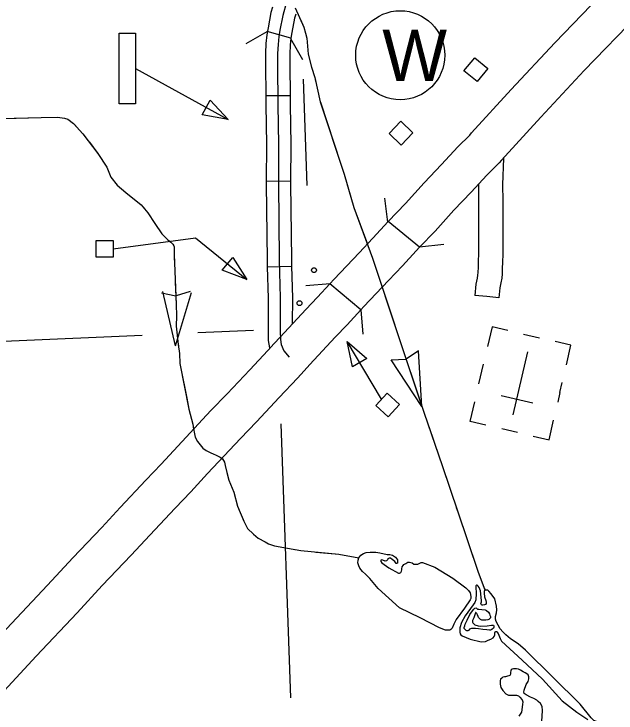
# Model space of a CAD drawing. Extents: x 1084508 to 1142749, y 1057638 to 1093403.
# Drawn here: x 1114355 to 1115521, y 1060091 to 1061446 of the extents above; entities that cross this region are included whole.
import ezdxf

# ---------------------------------------------------------------- set-up
doc = ezdxf.new("R2010")
doc.units = 0
for name, color, linetype in [('Level 15', 7, 'Continuous'), ('Level 32', 7, 'Continuous'), ('Level 35', 7, 'Continuous'), ('Level 37', 7, 'Continuous'), ('Level 38', 7, 'Continuous'), ('Level 43', 7, 'Continuous'), ('Level 46', 7, 'Continuous'), ('Level 5', 7, 'Continuous'), ('Level 56', 7, 'Continuous'), ('Level 57', 7, 'Continuous')]:
    doc.layers.add(name, color=color, linetype=linetype)

msp = doc.modelspace()

# ---------------------------------------------------------------- linework, layer by layer
at = {"layer": 'Level 15'}
for p, q in [((1115140.9, 1060993.5), (1115079.6, 1061043.1)), ((1115027.2, 1060872.2), (1114967, 1060922.7))]:
    msp.add_line(p, q, dxfattribs=at)
for points in [[(1115241.6, 1061215.1), (1115318.3, 1061299.1), (1115402.8, 1061389.8), (1115508.4, 1061499.3)], [(1115564.9, 1061444.8), (1115459.8, 1061335.8), (1115376, 1061245.9), (1115299.6, 1061162.2)], [(1115079.6, 1061043.1), (1115113.2, 1061078.1), (1115149.4, 1061118.6), (1115183.4, 1061154.1), (1115214.7, 1061187.9), (1115237.9, 1061211), (1115241.6, 1061215.1)], [(1115299.6, 1061162.2), (1115294.7, 1061156.8), (1115271.3, 1061133.5), (1115240.6, 1061100.3), (1115207, 1061065.3), (1115170.8, 1061024.8), (1115140.9, 1060993.5)], [(1115079.6, 1061043.1), (1115050.1, 1061010.9), (1115023.6, 1060982.9), (1114975.4, 1060931.8), (1114967, 1060922.7)], [(1115140.9, 1060993.5), (1115134, 1060986.4), (1115107.6, 1060957.4), (1115080.5, 1060928.9), (1115032.8, 1060878.3), (1115027.2, 1060872.2)], [(1114967, 1060922.7), (1114943.2, 1060896.7), (1114920.3, 1060872.8), (1114870.3, 1060819.1), (1114859, 1060806.8)], [(1114916.9, 1060753.8), (1114928, 1060765.9), (1114977.3, 1060818.9), (1115000.4, 1060843), (1115027.2, 1060872.2)], [(1114859, 1060806.8), (1114846.4, 1060793), (1114811.6, 1060755.8), (1114767.8, 1060709.4), (1114736.5, 1060676.9), (1114672.2, 1060608), (1114640.1, 1060572.8), (1114610, 1060541.7), (1114560.6, 1060488.9), (1114524.7, 1060450.4), (1114468.5, 1060391.1), (1114419.6, 1060338.5), (1114340.5, 1060254), (1114270.6, 1060179), (1114255.7, 1060163.4)], [(1114312.6, 1060109.4), (1114327.7, 1060125.1), (1114397.9, 1060200.5), (1114477, 1060285), (1114525.8, 1060337.5), (1114581.8, 1060396.7), (1114617.9, 1060435.3), (1114666.9, 1060487.6), (1114697.3, 1060519.1), (1114729.8, 1060554.8), (1114793.4, 1060622.8), (1114824.6, 1060655.2), (1114868.9, 1060702.1), (1114904, 1060739.7), (1114916.9, 1060753.8)]]:
    msp.add_lwpolyline(points, dxfattribs=at)
at = {"layer": 'Level 32'}
for p, q in [((1114891.2, 1061399), (1114845.6, 1061411.4)), ((1114842.6, 1061287.4), (1114889.7, 1061287.9)), ((1114843.6, 1061122.1), (1114890.7, 1061121.8)), ((1114845.6, 1060955.6), (1114892.7, 1060956.8))]:
    msp.add_line(p, q, dxfattribs=at)
for points in [[(1114883, 1061468.7), (1114875.6, 1061443), (1114870.2, 1061414.2), (1114867.8, 1061402.1), (1114866.4, 1061386.8), (1114865.5, 1061369), (1114865.4, 1061346.1), (1114866.3, 1061270.2), (1114867.6, 1061192.2), (1114867.1, 1061116.8), (1114868.8, 1060968.9), (1114870.8, 1060895.2), (1114870.5, 1060830.8), (1114871, 1060814.7), (1114872.7, 1060804.9), (1114877.9, 1060792.8), (1114887.9, 1060780.3)], [(1114855.6, 1061458.7), (1114852.7, 1061448.5), (1114847.1, 1061418.6), (1114844.5, 1061405.5), (1114842.9, 1061388.5), (1114842, 1061369.6), (1114841.9, 1061346), (1114842.6, 1061287.4)], [(1114900.8, 1061445.6), (1114898.5, 1061437.6), (1114893.3, 1061409.8), (1114891.2, 1061398.8), (1114889.9, 1061385.1), (1114889.1, 1061368.4), (1114889, 1061346.2), (1114889.7, 1061287.9)], [(1114842.6, 1061287.4), (1114842.8, 1061269.9), (1114844, 1061192.1), (1114843.6, 1061122.1)], [(1114889.7, 1061287.9), (1114889.9, 1061270.5), (1114891.1, 1061192.3), (1114890.7, 1061121.8)], [(1114843.6, 1061122.1), (1114843.6, 1061116.7), (1114845.3, 1060968.4), (1114845.6, 1060955.6)], [(1114890.7, 1061121.8), (1114890.7, 1061116.9), (1114892.4, 1060969.3), (1114892.7, 1060956.8)], [(1114845.6, 1060955.6), (1114847.2, 1060895), (1114847, 1060830.5), (1114847.5, 1060812.4), (1114849.9, 1060798.2), (1114850.3, 1060797.3)], [(1114892.7, 1060956.8), (1114894.3, 1060895.5), (1114894.1, 1060844.7)]]:
    msp.add_lwpolyline(points, dxfattribs=at)
at = {"layer": 'Level 35'}
for points in [[(1115239, 1060309.7), (1115227.6, 1060294), (1115211.9, 1060271.6), (1115207.1, 1060262.5), (1115204.2, 1060255.2), (1115201.6, 1060252.6), (1115199.1, 1060251.5), (1115194, 1060251.1), (1115190.7, 1060251.1), (1115179.3, 1060255.9), (1115141.6, 1060274.9), (1115101.7, 1060294.7), (1115081.3, 1060313.4), (1115060.4, 1060331.7), (1115044.3, 1060351.4), (1115035.9, 1060359.5), (1115030.4, 1060365), (1115024.9, 1060371.2), (1115023.1, 1060376), (1115021.2, 1060381.5), (1115021.6, 1060387), (1115022.7, 1060391.7), (1115027.1, 1060396.8), (1115032.2, 1060399.8), (1115037.3, 1060402), (1115045, 1060402.7), (1115050.9, 1060402.7), (1115056, 1060402.3), (1115063.7, 1060400.9), (1115078, 1060397.6), (1115083.4, 1060397.6), (1115088.2, 1060396.8), (1115094.4, 1060392.4), (1115098.1, 1060387.7), (1115098.1, 1060384.4), (1115098.1, 1060382.9), (1115097.7, 1060381.1), (1115096.3, 1060380.7), (1115095.5, 1060380.7), (1115094.1, 1060382.2), (1115092.6, 1060384.4), (1115090, 1060386.2), (1115087.8, 1060388.4), (1115084.2, 1060390.6), (1115082, 1060390.6), (1115079.4, 1060389.2), (1115078.7, 1060387.3), (1115076.5, 1060385.5), (1115074.3, 1060385.1), (1115073.9, 1060385.1), (1115069.5, 1060387), (1115067.3, 1060387.3), (1115065.9, 1060386.6), (1115065.9, 1060384), (1115067.7, 1060381.5), (1115081.3, 1060372.3), (1115099.9, 1060361.7), (1115101.7, 1060361.7), (1115104.7, 1060362.8), (1115105.8, 1060365.7), (1115106.1, 1060367.9), (1115106.1, 1060370.1), (1115107.2, 1060373.8), (1115108.7, 1060376.3), (1115110.5, 1060378.5), (1115113.8, 1060380.4), (1115117.8, 1060382.9), (1115121.5, 1060382.9), (1115126.3, 1060381.8), (1115129.9, 1060379.3), (1115134.7, 1060379.3), (1115137.6, 1060379.3), (1115139.8, 1060380.4), (1115143.5, 1060382.6), (1115146.4, 1060382.6), (1115170.5, 1060373), (1115205.3, 1060352.2), (1115230.2, 1060333.1), (1115235.3, 1060328), (1115239, 1060323.6), (1115239.7, 1060320.3), (1115240.1, 1060315.9), (1115240.1, 1060312.8), (1115239.7, 1060311.2), (1115239, 1060309.7)], [(1115288.1, 1060277.6), (1115289.9, 1060285.1), (1115290.2, 1060290.8), (1115289.9, 1060297.7), (1115286.3, 1060312.1), (1115279.4, 1060321.7), (1115275.2, 1060326.5), (1115272.8, 1060328.6), (1115271.9, 1060328.6), (1115269.2, 1060328.6), (1115267.3, 1060328.6), (1115266.3, 1060327.9), (1115265.9, 1060326.1), (1115265.9, 1060323.2), (1115266.6, 1060315.5), (1115269.2, 1060308.6), (1115269.9, 1060305.3), (1115269.7, 1060303.2), (1115268.2, 1060301), (1115266.7, 1060300), (1115263.5, 1060299.7), (1115261.9, 1060299.7), (1115260.5, 1060300.6), (1115260.1, 1060301.2), (1115259.7, 1060302.5), (1115259.8, 1060303.9), (1115260.5, 1060305.8), (1115260.8, 1060309), (1115258.7, 1060327.4), (1115256.1, 1060334.1), (1115254.5, 1060336.8), (1115253.2, 1060338), (1115252.1, 1060338.3), (1115251.2, 1060338.3), (1115250, 1060337.2), (1115249.7, 1060335.5), (1115250.3, 1060322.3), (1115249.7, 1060310.1), (1115247.6, 1060304.8), (1115244.8, 1060300), (1115229.1, 1060278.9), (1115222.1, 1060265.9), (1115219, 1060255.8), (1115218.5, 1060250.7), (1115218.8, 1060247.4), (1115219.1, 1060244.2), (1115220.6, 1060242.3), (1115223.1, 1060239.9), (1115238.8, 1060233.8), (1115259.8, 1060228.4), (1115268.4, 1060229), (1115273.8, 1060232), (1115279.1, 1060233.9), (1115283.4, 1060236.3), (1115285.3, 1060238.7), (1115286.6, 1060242.1), (1115286.3, 1060244.4), (1115286.3, 1060245.9), (1115287.5, 1060248.2), (1115288.4, 1060248.7), (1115289.5, 1060248.7)], [(1115276.3, 1060251.3), (1115270.9, 1060252), (1115263, 1060252.8), (1115255.2, 1060254), (1115249.1, 1060254.2), (1115245.1, 1060254.2), (1115241.5, 1060254.2), (1115239.7, 1060253.9), (1115237.8, 1060253.1), (1115236.1, 1060251.2), (1115235.3, 1060250.4), (1115234, 1060249.9), (1115232.3, 1060249.9), (1115230.7, 1060250.5), (1115228.3, 1060252.9), (1115227.1, 1060254.3), (1115227.1, 1060256.1), (1115228.2, 1060259.3), (1115229.3, 1060262.7), (1115232.8, 1060270.5), (1115238.1, 1060281.7), (1115243.2, 1060288.4), (1115245.6, 1060291.9), (1115247.5, 1060293.6), (1115249.9, 1060294.4), (1115250.8, 1060294.1), (1115251.9, 1060293), (1115253, 1060291.9), (1115255.7, 1060291.6), (1115261.3, 1060291.2), (1115267.9, 1060290.6), (1115270.4, 1060289.5), (1115274.2, 1060286.3), (1115276.3, 1060283), (1115277.1, 1060280.3), (1115277.9, 1060277.8), (1115277.9, 1060275.4), (1115276.9, 1060273.7), (1115276.4, 1060272.9), (1115275, 1060272.1), (1115273.1, 1060271.1), (1115269, 1060270.8)], [(1115269, 1060270.8), (1115265.5, 1060270.7), (1115261.6, 1060270.8), (1115258.9, 1060272.1), (1115256.8, 1060273.8), (1115255.1, 1060275.9), (1115254.1, 1060277.6), (1115253, 1060281), (1115252.1, 1060282.4), (1115251.8, 1060283.6), (1115250.6, 1060284.8), (1115250, 1060285.2), (1115249.2, 1060285.2), (1115248.9, 1060284.9), (1115248.3, 1060282.9), (1115248, 1060280.8), (1115245.9, 1060274.9), (1115243.2, 1060269.9), (1115243.2, 1060268.3), (1115243.2, 1060267), (1115243.7, 1060265.6), (1115245.7, 1060263.4), (1115248, 1060261.5), (1115254, 1060259.9), (1115258.2, 1060258.9), (1115271.7, 1060259.3), (1115279.8, 1060261), (1115282.3, 1060261.2), (1115284, 1060260.8), (1115284.4, 1060259.6), (1115284.8, 1060258.1), (1115284.7, 1060256.4), (1115283.7, 1060255), (1115281, 1060252.8), (1115278, 1060251.3), (1115276.3, 1060251.3)], [(1115524.5, 1060072.2), (1115520.2, 1060070.7), (1115511.8, 1060068.2), (1115508.6, 1060068.2), (1115504.3, 1060068.2), (1115498, 1060069.4), (1115489.9, 1060071.6), (1115478.4, 1060076), (1115473.4, 1060081), (1115452.2, 1060107.8), (1115346.1, 1060212.7), (1115331.6, 1060224.8), (1115316.9, 1060234.7), (1115307.6, 1060241.9), (1115302.2, 1060247.9), (1115296.8, 1060253.9), (1115289, 1060268.3), (1115287.8, 1060272.2), (1115288.1, 1060277.6)], [(1115289.5, 1060248.7), (1115290.6, 1060247.9), (1115292.8, 1060244.6), (1115296.9, 1060235.1), (1115299.7, 1060230), (1115339.3, 1060193.2), (1115379.1, 1060156), (1115416.9, 1060114.3), (1115445.6, 1060092), (1115466.5, 1060078)], [(1115377.8, 1060073.9), (1115379.1, 1060095.2), (1115378.4, 1060103.5), (1115374.9, 1060108.9), (1115370.8, 1060112.7), (1115367.9, 1060115.3), (1115362.2, 1060118.8), (1115355.9, 1060121.6), (1115347.3, 1060126.1), (1115343.5, 1060128.6), (1115342.5, 1060130.9), (1115343.1, 1060134.7), (1115347.6, 1060146.1), (1115351.1, 1060151.5), (1115352.7, 1060156.9), (1115352.7, 1060160.8), (1115351.1, 1060164.3), (1115348.9, 1060166.8), (1115345.4, 1060168.7), (1115341.2, 1060170.6), (1115336.5, 1060173.5), (1115332.3, 1060175.4), (1115328.5, 1060176.4), (1115326, 1060176.4), (1115322.8, 1060176), (1115320.2, 1060175.7), (1115318, 1060174.4), (1115317.7, 1060172.2), (1115316.7, 1060170), (1115316.7, 1060165.9), (1115315.8, 1060163.6), (1115313.6, 1060162.4), (1115311, 1060162), (1115307.2, 1060160.8), (1115305, 1060160.8), (1115301.8, 1060159.8), (1115299.9, 1060158.2), (1115297.7, 1060156), (1115296.7, 1060152.8), (1115297, 1060146.4), (1115298, 1060140.1)], [(1115298, 1060140.1), (1115301.8, 1060134.4), (1115307.8, 1060127.7), (1115312.9, 1060125.4), (1115318.3, 1060125.1), (1115323.4, 1060125.1), (1115328.8, 1060125.1), (1115332.3, 1060123.9), (1115335.2, 1060121), (1115339.3, 1060115.9), (1115340.6, 1060112.4), (1115340.3, 1060107), (1115338, 1060092), (1115333, 1060084.7)]]:
    msp.add_lwpolyline(points, dxfattribs=at)
at = {"layer": 'Level 37'}
for points in [[(1115079.2, 1061042.1), (1115073.7, 1061088.8)], [(1115187.6, 1060999.1), (1115140.9, 1060993.5)], [(1114920.4, 1060919.1), (1114967.3, 1060922.9)], [(1115027.2, 1060872.2), (1115031, 1060825.2)]]:
    msp.add_lwpolyline(points, dxfattribs=at)
at = {"layer": 'Level 38'}
for points in [[(1114804.4, 1061388.6), (1114845.6, 1061411.4)], [(1114890.9, 1061398.4), (1114913.7, 1061357.2)]]:
    msp.add_lwpolyline(points, dxfattribs=at)
at = {"layer": 'Level 43'}
for p, q in [((1114640.4, 1060905.2), (1114668.4, 1060899.1)), ((1114667.9, 1060802.5), (1114643.1, 1060907.4)), ((1114667.9, 1060802.5), (1114698.9, 1060905.7)), ((1114696.1, 1060907.8), (1114668.8, 1060899.1)), ((1115138.6, 1060792.5), (1115114.6, 1060776.7)), ((1115145, 1060685), (1115138.6, 1060792.5)), ((1115085.7, 1060774.9), (1115114.3, 1060776.6)), ((1115145, 1060685), (1115085.7, 1060774.9))]:
    msp.add_line(p, q, dxfattribs=at)
for points in [[(1114899.7, 1061457.7), (1114916.5, 1061420.4), (1114919.7, 1061408.5), (1114922, 1061398.5), (1114924.7, 1061367.9), (1114931.1, 1061342.4), (1114937.5, 1061322.3), (1114948.4, 1061275.4), (1114994.5, 1061135.4), (1115013.6, 1061070.7), (1115049.2, 1060972.6), (1115096.6, 1060830.4), (1115149.4, 1060671.7), (1115184.5, 1060570.5), (1115214.6, 1060480.7), (1115254.3, 1060363.9), (1115267.5, 1060329.3)], [(1114909.9, 1061435), (1114916.5, 1061420.4), (1114919.7, 1061408.5), (1114922, 1061398.5), (1114924.7, 1061367.9), (1114931.1, 1061342.4), (1114937.5, 1061322.3), (1114939.2, 1061314.9)], [(1114948.7, 1061274.6), (1114987.5, 1061156.5)], [(1114334.5, 1061242.8), (1114407.2, 1061245.1), (1114439.3, 1061245.7), (1114452.6, 1061243.9), (1114458.8, 1061241.9), (1114470, 1061233.3), (1114488.3, 1061213.2)], [(1114355.4, 1061243.4), (1114407.2, 1061245.1), (1114439.3, 1061245.7), (1114452.6, 1061243.9), (1114458.8, 1061241.9), (1114470, 1061233.3), (1114474.3, 1061228.7)], [(1114488.3, 1061213.2), (1114517.3, 1061175.4), (1114534.4, 1061148.5), (1114542.7, 1061129.3), (1114554.5, 1061114), (1114571.3, 1061099.8), (1114601.4, 1061075.6), (1114607.9, 1061067.9), (1114614.1, 1061059.9), (1114627.7, 1061039.3), (1114641.3, 1061019.2), (1114653.1, 1061008), (1114658.4, 1061003.2), (1114662.5, 1060999.7), (1114664.3, 1060996.4), (1114665.2, 1060994.1), (1114664.9, 1060979.3), (1114669.3, 1060882.7), (1114669.6, 1060860.3), (1114669, 1060840.8), (1114673.1, 1060805.1), (1114675.2, 1060787.3), (1114676.4, 1060768.4), (1114693.5, 1060679.8), (1114701.5, 1060650.6), (1114703.9, 1060635), (1114705.6, 1060625.5), (1114710.1, 1060616.9), (1114721, 1060603.9), (1114726.9, 1060599.2), (1114736, 1060594.8), (1114740.5, 1060593.3), (1114746.4, 1060590.7), (1114754.6, 1060586.5), (1114758.8, 1060583), (1114762.6, 1060576.8), (1114764.1, 1060570.3), (1114767, 1060557), (1114770.9, 1060542.2), (1114780.6, 1060518.7), (1114788.1, 1060491.7), (1114800.2, 1060462.8), (1114807.2, 1060448.4), (1114818.8, 1060437.2), (1114827.7, 1060429.7), (1114841.6, 1060422.7), (1114847.7, 1060418.5), (1114859.8, 1060414.8), (1114884.5, 1060410.2), (1114910.5, 1060405.5), (1114984.1, 1060398.5), (1115022.7, 1060391.7)], [(1114500.8, 1061196.9), (1114517.3, 1061175.4), (1114534.4, 1061148.5), (1114542.7, 1061129.3), (1114554.5, 1061114), (1114571.3, 1061099.8), (1114573.7, 1061097.9)], [(1114999.9, 1061117), (1115013.6, 1061070.7), (1115039.5, 1060999.2)], [(1114605.2, 1061071.1), (1114607.9, 1061067.9), (1114614.1, 1061059.9), (1114627.7, 1061039.3), (1114641.3, 1061019.2), (1114653.1, 1061008), (1114658.4, 1061003.2), (1114662.5, 1060999.7), (1114664.3, 1060996.4), (1114665.2, 1060994.1), (1114664.9, 1060979.3), (1114665.4, 1060968.1)], [(1114667.3, 1060926.7), (1114669.3, 1060882.7), (1114669.6, 1060860.3), (1114669, 1060840.8), (1114673.1, 1060805.1), (1114673.4, 1060802.7)], [(1115068.1, 1060915.8), (1115092.6, 1060842.2)], [(1115105.7, 1060802.9), (1115145, 1060685)], [(1114677.7, 1060761.6), (1114689.5, 1060700.6)], [(1114689.5, 1060700.6), (1114693.5, 1060679.8), (1114701.5, 1060650.6), (1114702.9, 1060640.9)], [(1115158.4, 1060645.8), (1115178.8, 1060587.1)], [(1114757.3, 1060584.2), (1114758.8, 1060583), (1114762.6, 1060576.8), (1114764.1, 1060570.3), (1114767, 1060557), (1114770.9, 1060542.2), (1114780.6, 1060518.7), (1114784, 1060506.6)], [(1115178.8, 1060587.1), (1115184.5, 1060570.5), (1115198.7, 1060528.2)], [(1115211.8, 1060488.9), (1115214.6, 1060480.7), (1115251.8, 1060371.2)], [(1114798.1, 1060467.7), (1114800.2, 1060462.8), (1114807.2, 1060448.4), (1114818.8, 1060437.2), (1114827.7, 1060429.7), (1114841.6, 1060422.7), (1114847.7, 1060418.5), (1114859.8, 1060414.8), (1114884.5, 1060410.2), (1114898.7, 1060407.6)], [(1114939.8, 1060402.7), (1114984.1, 1060398.5), (1115022.7, 1060391.7)], [(1115266.3, 1060332.4), (1115267.5, 1060329.3)]]:
    msp.add_lwpolyline(points, dxfattribs=at)
at = {"layer": 'Level 46'}
for points in [[(1115303.4, 1061166.4), (1115301.7, 1061114.4), (1115301.8, 1061083.5), (1115302.1, 1061063.7), (1115301.8, 1061020.1), (1115301.8, 1060980.1), (1115301.5, 1060964.8), (1115301, 1060952.5), (1115300.5, 1060942.1), (1115300.2, 1060933.7), (1115298.3, 1060924.6), (1115296.5, 1060914.9), (1115294.6, 1060895.6), (1115271.1, 1060897.9), (1115247.7, 1060900.2)], [(1115254.6, 1061115.4), (1115254.7, 1061083.1), (1115255, 1061063.6), (1115254.7, 1061020.2), (1115254.7, 1060980.5), (1115254.5, 1060966.2), (1115254, 1060954.6), (1115253.5, 1060944.2), (1115253.3, 1060939.4), (1115252.1, 1060933.7), (1115249.9, 1060921.6), (1115247.7, 1060900.2)]]:
    msp.add_lwpolyline(points, dxfattribs=at)
at = {"layer": 'Level 5'}
for points in [[(1114711, 1060827.9), (1114818.8, 1060832.7)], [(1114110.9, 1060801.5), (1114603.2, 1060823.2)], [(1114872.1, 1060651.4), (1114890.3, 1060119.7)]]:
    msp.add_lwpolyline(points, dxfattribs=at)
at = {"layer": 'Level 56'}
for p, q in [((1114719.7, 1061250.2), (1114735.2, 1061278.3)), ((1114735.2, 1061278.3), (1114769.5, 1061241)), ((1114769.5, 1061241), (1114719.7, 1061250.2)), ((1114758.5, 1060948.8), (1114778.7, 1060973.6)), ((1114778.7, 1060973.6), (1114805.8, 1060930.9)), ((1114805.8, 1060930.9), (1114758.5, 1060948.8)), ((1115011, 1060761.5), (1115000.2, 1060811)), ((1115000.2, 1060811), (1115038.5, 1060777.9)), ((1115038.5, 1060777.9), (1115011, 1060761.5))]:
    msp.add_line(p, q, dxfattribs=at)
for points in [[(1114558.8, 1061408.6), (1114590.2, 1061408.6), (1114590.2, 1061271.3), (1114558.8, 1061271.3)], [(1115252.1, 1061314.8), (1115226.8, 1061335.5), (1115247.5, 1061360.8), (1115272.8, 1061340.2)], [(1115105.2, 1061191.6), (1115081.5, 1061214.1), (1115104.2, 1061237.9), (1115127.8, 1061215.3)], [(1114514.1, 1060974.1), (1114514.1, 1061006.7), (1114546.9, 1061006.7), (1114546.9, 1060974.1)], [(1115079.8, 1060664.6), (1115055.8, 1060686.7), (1115078, 1060710.8), (1115102, 1060688.7)]]:
    msp.add_lwpolyline(points, close=True, dxfattribs=at)
for points in [[(1114590.2, 1061339.9), (1114769.5, 1061241)], [(1114914.9, 1061319.1), (1114922, 1061113.3)], [(1114546.9, 1060990.4), (1114706.2, 1061011.9), (1114805.8, 1060930.9)], [(1115066.9, 1060698.8), (1115000.2, 1060811)]]:
    msp.add_lwpolyline(points, dxfattribs=at)
for centre in [(1114936.1, 1060949), (1114908, 1060885.2)]:
    msp.add_circle(centre, 4.71, dxfattribs=at)
at = {"layer": 'Level 57'}
for p, q in [((1115342.4, 1060824.9), (1115373, 1060817.8)), ((1115322.2, 1060668.5), (1115350.5, 1060790.8)), ((1115255.5, 1060728.4), (1115264.4, 1060766.7)), ((1115336.4, 1060729.6), (1115336.4, 1060729.6)), ((1115336.4, 1060729.6), (1115336.4, 1060729.6)), ((1115412.8, 1060712), (1115417.3, 1060731.4)), ((1115298.7, 1060706.1), (1115360.2, 1060691.9)), ((1115412.8, 1060712), (1115408.5, 1060693.1)), ((1115330.6, 1060634.3), (1115300.1, 1060641.4))]:
    msp.add_line(p, q, dxfattribs=at)
for points in [[(1115311.7, 1060832), (1115281.1, 1060839), (1115272.3, 1060800.8)], [(1115425.2, 1060765.5), (1115434, 1060803.7), (1115403.4, 1060810.8)], [(1115269.3, 1060648.5), (1115238.7, 1060655.5), (1115247.5, 1060693.8)], [(1115361.1, 1060627.3), (1115391.6, 1060620.2), (1115400.5, 1060658.5)]]:
    msp.add_lwpolyline(points, dxfattribs=at)
msp.add_circle((1115103.3, 1061365.6), 86.3, dxfattribs=at)

# ---------------------------------------------------------------- texts
msp.add_text('W', height=99.4, dxfattribs=at).set_placement((1115068.5, 1061315.8))

doc.saveas('drawing.dxf')
